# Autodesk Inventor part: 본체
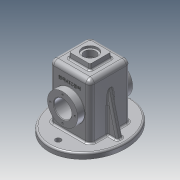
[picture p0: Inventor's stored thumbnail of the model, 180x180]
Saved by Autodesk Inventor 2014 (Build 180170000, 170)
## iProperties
Created: 2017-07
Part Number: 본체
Material: 알루미늄 6061
Document SubType Name: Modeling
Designer: user
Density: 2.71 g/cm^3
Appearance: 알루미늄 - 평지
Mass: 892.712 g
Surface Area: 987.354 cm^2
Volume: 329.414 cm^3
Author: user
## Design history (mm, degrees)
sketch "스케치1"
  geometry: C1 r 27.5 at (0, 0); 1 further point
  constraints: 1 centre point, 1 coincident
  dimensions: "d0" = 55 diameter of C1
extrude "돌출1" new body sketch "스케치1" stored distance "d1" = 100; taper "d2" = 0 deg
node "작업 평면1"
sketch "스케치2" dims "d4" = 65, "d5" = 75
  geometry: 2 further points; 1 other entity
  constraints: 1 coincident, 2 other
extrude "돌출2" join sketch "스케치2" distance "d6" = 10; taper "d7" = 0 deg
sketch "스케치3"
  geometry: L1 (-37, 37)-(37, 37); L2 (37, 37)-(37, -37); L3 (37, -37)-(-37, -37); L4 (-37, -37)-(-37, 37); L5 (-37, 37)-(37, -37); L6 (37, 37)-(-37, -37); 1 further point; 1 other entity
  constraints: 12 end point, 2 midpoint, 2 parallel, 1 horizontal, 1 perpendicular, 1 other
  dimensions: "d8" = 74 distance of L2.end L3.end; "d9" = 74 distance of L1.end L2.end
extrude "돌출3" join sketch "스케치3" distance "d10" = 100; taper "d11" = 0 deg
sketch "스케치4"
  geometry: L1 (-20, -20)-(20, -20); L2 (20, -20)-(20, 20); L3 (20, 20)-(-20, 20); L4 (-20, 20)-(-20, -20); L5 (-20, -20)-(20, 20); L6 (20, -20)-(-20, 20); 1 further point
  constraints: 12 end point, 2 midpoint, 2 parallel, 1 horizontal, 1 perpendicular
  dimensions: "d12" = 40 distance of L3.end L2.end; "d13" = 40 distance of L2.end L1.end
extrude "돌출4" join sketch "스케치4" distance "d14" = 10; taper "d15" = 0 deg
fillet "모깎기1" dims "d16" = 8
sketch "스케치5"
  geometry: L1 (-45, -75)-(-55, -75) reference; L2 (-55, -75)-(-55, 75) reference; L3 (-55, 75)-(-45, 75) reference; L4 (-45, 75)-(-45, 37) reference; L5 (-45, 37)-(-27.5, 37) reference; L6 (-27.5, 37)-(-27.5, 50) reference; L7 (-27.5, 50)-(27.5, 50) reference; L8 (27.5, 50)-(27.5, 37) reference; L9 (27.5, 37)-(55, 37) reference; L10 (55, 37)-(55, 20) reference; L11 (55, 20)-(65, 20) reference; L12 (65, 20)-(65, -20) reference; L13 (65, -20)-(55, -20) reference; L14 (55, -20)-(55, -37) reference; L15 (55, -37)-(27.5, -37) reference; L16 (27.5, -37)-(27.5, -50) reference; L17 (27.5, -50)-(-27.5, -50) reference; L18 (-27.5, -50)-(-27.5, -37) reference; L19 (-27.5, -37)-(-45, -37) reference; L20 (-45, -37)-(-45, -75) reference; L21 (-55, 32)-(50, 32); L22 (50, 32)-(50, -32); L23 (50, -32)-(-55, -32); L24 (-55, -32)-(-55, 32); 2 further points
  constraints: 8 end point, 2 parallel, 1 horizontal, 1 midpoint, 1 perpendicular, 1 point on line
  dimensions: "d17" = 5 distance between parallel lines of L10 L22; "d18" = 5 distance between parallel lines of L9 L21; "d19" = 5 distance between parallel lines of L15 L23
extrude "돌출5" cut sketch "스케치5" stored distance "d20" = 64; taper "d21" = 0 deg
node "작업 평면2"
sketch "스케치6"
  geometry: 1 further point
sketch "스케치7"
  geometry: C1 r 27.5 at (32, 55); 1 further point
  constraints: 1 centre point, 1 coincident
  dimensions: "d23" = 55 diameter of C1
extrude "돌출6" join sketch "스케치7" distance "d24" = 7; taper "d25" = -45 deg
hole "구멍1" diameter "d28" = 32; stored, may be unused: countersink angle "d32" = 90 deg, drill point angle "d34" = 118 deg; dims "d26" = 10, "d27" = 10, "d29" = 6, "d30" = 4, "d31" = 2, "d33" = 8
sketch "스케치8" dims "d35" = 45
  geometry: C1 r 27.5 at (0, 0) reference; 2 further points
  constraints: 2 vertical alignment, 1 coincident, 2 other
hole "구멍2" sketch "스케치8" at (0, 22.5) diameter "d36" = 3.242; stored, may be unused: countersink angle "d40" = 90 deg, drill point angle "d42" = 118 deg; dims "d37" = 8, "d38" = 4, "d39" = 2, "d41" = 10
sketch "스케치9"
  geometry: 2 further points
  constraints: 1 coincident
hole "구멍3" sketch "스케치9" at (0, 0) diameter "d46" = 21; stored, may be unused: countersink angle "d50" = 90 deg, drill point angle "d52" = 118 deg; dims "d47" = 8, "d48" = 28, "d49" = 4, "d51" = 10
feature "면 기울기1" dims angle "d53" = 5 deg
sketch "스케치11"
  geometry: L1 (65, -45)-(65, -55) reference; L2 (65, -55)-(32, -55) reference; L3 (32, -55)-(32, 50) reference; L4 (32, 50)-(10.5, 50) reference; L5 (10.5, 50)-(10.5, 61) reference; L6 (10.5, 61)-(14, 61) reference; L7 (14, 61)-(14, 65) reference; L8 (14, 65)-(19.125, 65) reference; L9 (19.125, 65)-(20, 55) reference; L10 (20, 55)-(37, 55) reference; L11 (37, 55)-(37, -45) reference; L12 (37, -45)-(65, -45) reference; L13 (-65, -55)-(-65, -45) reference; L14 (-65, -45)-(-37, -45) reference; L15 (-37, -45)-(-37, 55) reference; L16 (-37, 55)-(-20, 55) reference; L17 (-20, 55)-(-19.125, 65) reference; L18 (-19.125, 65)-(-14, 65) reference; L19 (-14, 65)-(-14, 61) reference; L20 (-14, 61)-(-10.5, 61) reference; L21 (-10.5, 61)-(-10.5, 50) reference; L22 (-10.5, 50)-(-32, 50) reference; L23 (-32, 50)-(-32, -55) reference; L24 (-32, -55)-(-65, -55) reference; L25 (-55, -45)-(-45.492, -6.867); 1 further point
  constraints: 2 end point, 1 point on line
  dimensions: "d54" = 10 distance from line of L25.start L13; "d55" = 14 deg angle of L13 L25
feature "리브1" sketch "스케치11" dims "d56" = 1, "d57" = 10, "d58" = 0, "d59" = 0, "d60" = 1, "d61" = 1
sketch "스케치12"
  geometry: L1 (0, 58)-(0, -58); 2 further points; 1 other entity
  constraints: 2 end point, 1 coincident, 1 midpoint, 1 vertical, 1 other
  dimensions: "d62" = 116 distance of L1.start L1.end
hole "구멍4" sketch "스케치12" at (0, -58), (0, 58) diameter "d63" = 10; stored, may be unused: countersink angle "d67" = 90 deg, drill point angle "d69" = 118 deg; dims "d64" = 8, "d65" = 28, "d66" = 4, "d68" = 10
fillet "모깎기2" dims "d70" = 3
fillet "모깎기3" dims "d71" = 3
fillet "모깎기4" dims "d72" = 3
fillet "모깎기5" dims "d73" = 3
fillet "모깎기6" dims "d74" = 8
chamfer "모따기1" distance "d77" = 1; stored, may be unused: second distance "d78" = 2, angle "d79" = 45 deg
fillet "모깎기9" dims "d80" = 3
fillet "모깎기10" dims "d81" = 3
fillet "모깎기11" dims "d82" = 3
sketch "스케치13"
  geometry: L1 (66, -89)-(66, 0) reference; L2 (45.137, 18)-(48.125, 18) reference; 1 further point
  constraints: 1 other
  dimensions: "d84" = 37 distance from line of L1 point (29, -12); "d85" = 30 distance from line of L2 point (29, -12)
feature "엠보싱1" sketch "스케치13" dims "d0" = 55, "d86" = 0.5, "d87" = 0
fillet "모깎기13" dims "d88" = 0.5
fillet "모깎기14" dims "d89" = 0.5
node "솔리드1"
mirror "대칭1"
pattern_circular "원형 패턴1" dims angle "d44" = 360 deg
mirror "대칭2"
mirror "대칭3"
node "절단 모서리 투영1"
node "절단 모서리 투영2"
other parameters: "d3" = -55, "d22" = 7
